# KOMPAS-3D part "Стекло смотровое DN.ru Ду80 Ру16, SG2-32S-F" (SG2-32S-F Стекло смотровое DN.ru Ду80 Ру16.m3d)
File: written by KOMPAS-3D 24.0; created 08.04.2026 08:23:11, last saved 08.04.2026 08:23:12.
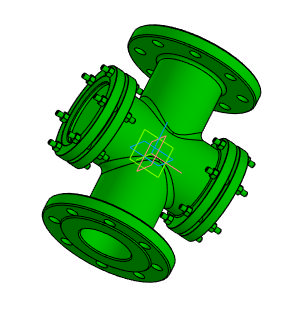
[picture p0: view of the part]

Document properties: Автор: Main; Полное имя файла: D:\DN.ru Аутсерс\Стекло смотровое DN.ru\SG2-32S-F Стекло смотровое DN.ru Ду80 Ру16\SG2-32S-F Стекло смотровое DN.ru Ду80 Ру16.m3d

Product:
- Body: Тело 1  | qty 1
    Масса: 19.954238
- Part/product: Стекло смотровое DN.ru Ду80 Ру16  | designation SG2-32S-F
    Масса: 20.5
    Раздел спецификации: Прочие изделия
    Примечание: D500-00110

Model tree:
1. Операция без истории:1

Expressions: SG2-32S-F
